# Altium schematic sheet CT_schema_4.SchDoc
size 284 x 211 mm
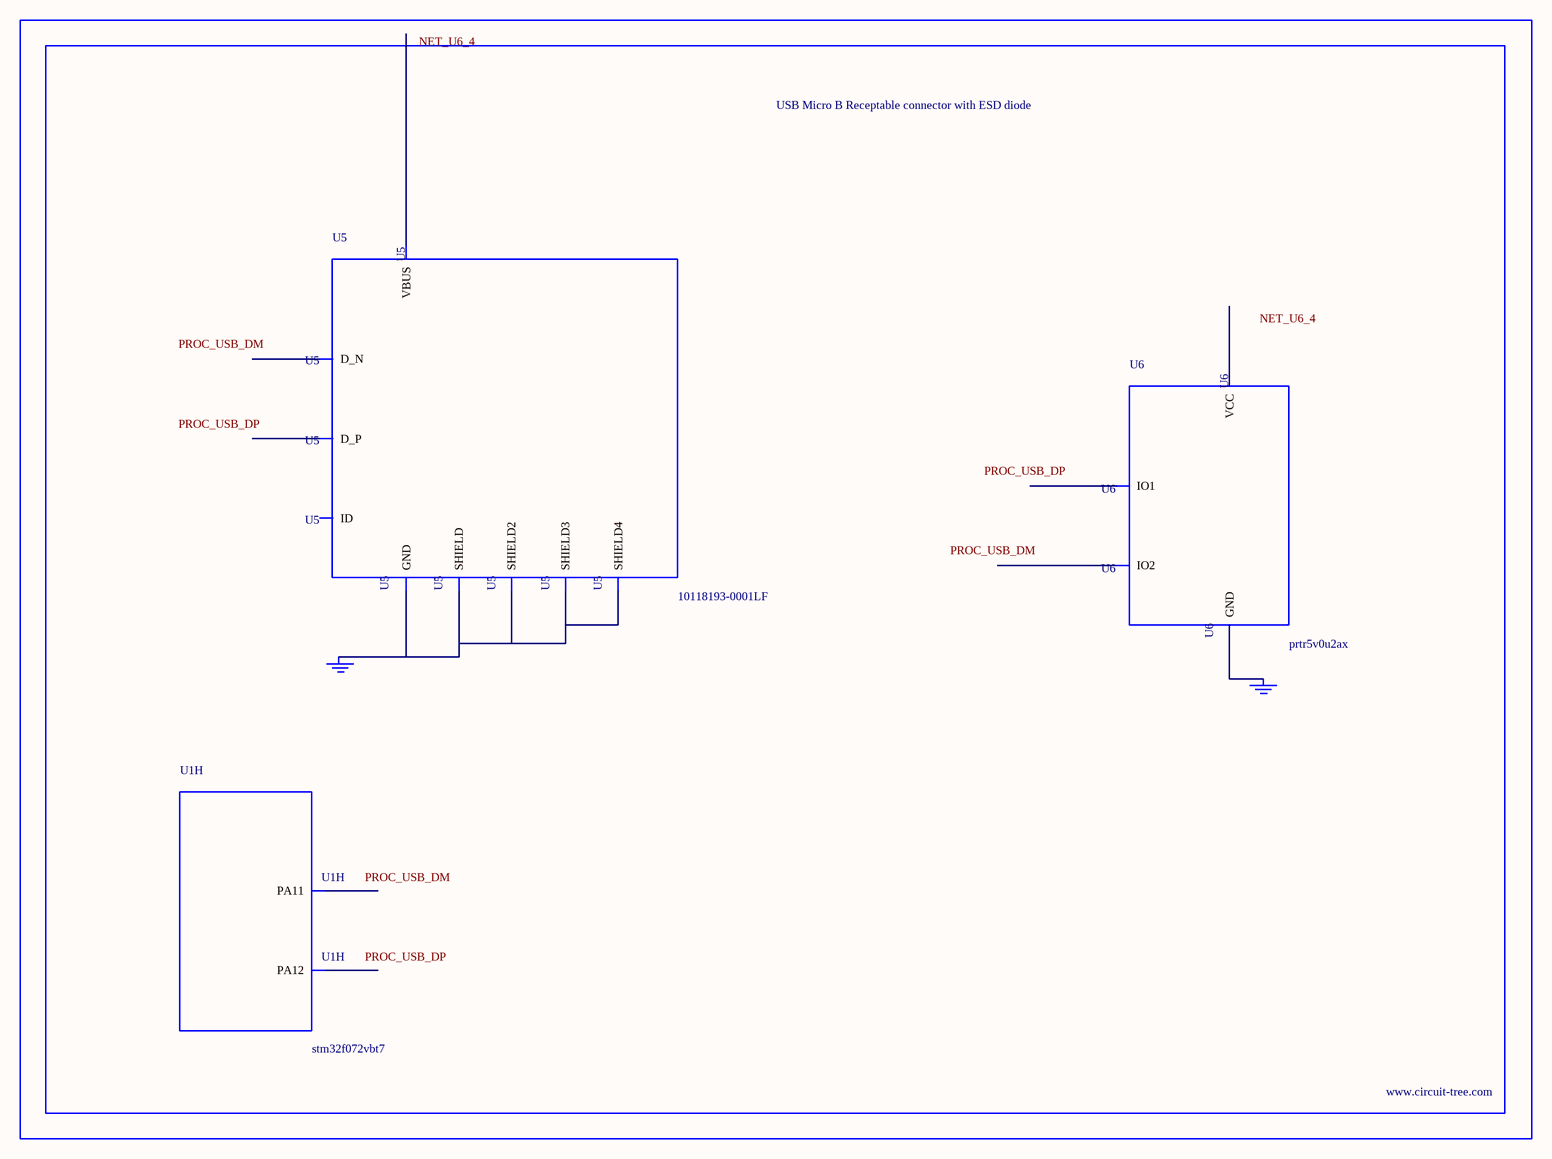
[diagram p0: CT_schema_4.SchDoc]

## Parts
BORDER3  (no value)
GND_INSTANCE_3_0  (no value)
GND_INSTANCE_3_1  (no value)
U1  stm32f072vbt7  [LQFP100]  (part H of 10)
U5  10118193-0001LF  [FCI_10118193-0001LF]
U6  prtr5v0u2ax  [SOT143B]

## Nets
NetGND_INSTANCE_3_0_0: GND_INSTANCE_3_0.0(GND) U5.5(GND) U5.6(SHIELD) U5.7(SHIELD2) U5.8(SHIELD3) U5.9(SHIELD4)
NetGND_INSTANCE_3_1_0: GND_INSTANCE_3_1.0(GND) U6.1(GND)

Not connected (* = marked no-connect by the designer): U1 70(PA11) 71(PA12); U5 1(VBUS) 2(D_N) 3(D_P) 4(ID); U6 2(IO1) 3(IO2) 4(VCC)

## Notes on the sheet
- Labels drawn without touching a wire or pin: NET_U6_4, PROC_USB_DM, PROC_USB_DP

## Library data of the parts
BORDER3 = BORDER_PAGE3
GND_INSTANCE_3_0 GND_INSTANCE_3_1 = GND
